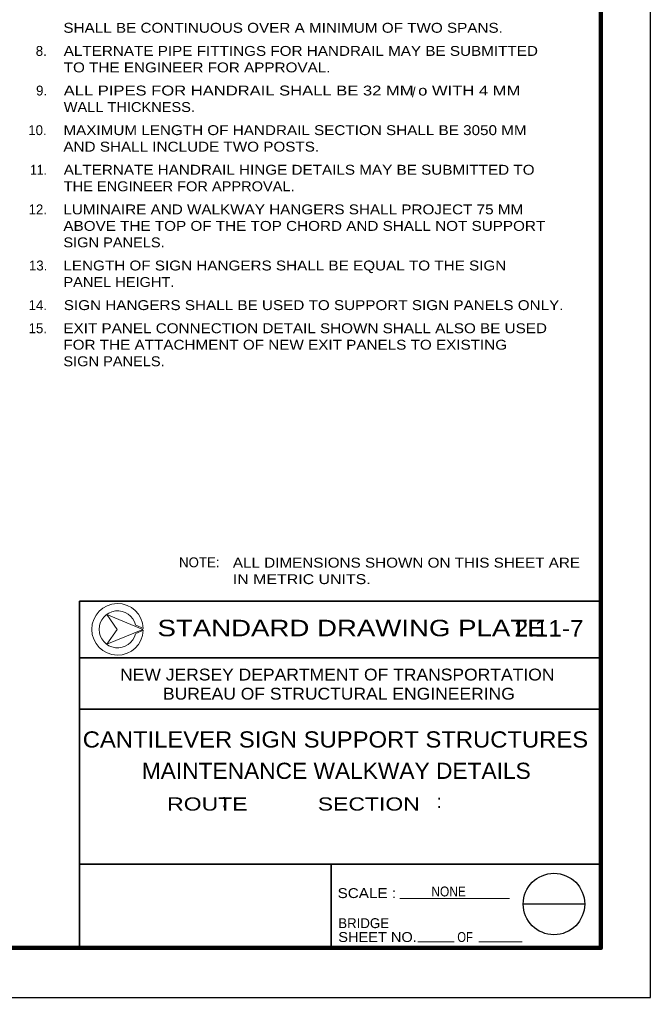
# Model space of a CAD drawing. Extents: x 312601.858 to 312602.699, y 144420.109 to 144420.704.
# Drawn here: x 312602.5078 to 312602.6988, y 144420.1095 to 144420.4057 of the extents above; entities that cross this region are included whole.
import ezdxf
from ezdxf.enums import TextEntityAlignment as Align

# ---------------------------------------------------------------- set-up
doc = ezdxf.new("R2010")
doc.units = 0
doc.header["$LTSCALE"] = 0.0012
for name, color, linetype, lineweight in [('1', 7, 'Continuous', 13), ('2', 7, 'Continuous', 13), ('39', 7, 'Continuous', 13), ('4', 7, 'Continuous', 13)]:
    doc.layers.add(name, color=color, linetype=linetype, lineweight=lineweight)

msp = doc.modelspace()

# ---------------------------------------------------------------- linework, layer by layer
at = {"layer": '1'}
msp.add_line((312602.543, 144420.2197), (312602.5453, 144420.2207), dxfattribs=at)
for points in [[(312602.5451, 144420.221), (312602.5342, 144420.2255), (312602.5451, 144420.221)], [(312602.5453, 144420.2213), (312602.543, 144420.2223), (312602.5429, 144420.2223)]]:
    msp.add_lwpolyline(points, dxfattribs=at)
for points in [[(312602.5451, 144420.221), (312602.5342, 144420.2255), (312602.5374, 144420.221), (312602.5342, 144420.2165)], [(312602.5374, 144420.221), (312602.5342, 144420.2165), (312602.5451, 144420.221), (312602.5342, 144420.2255)]]:
    msp.add_lwpolyline(points, close=True, dxfattribs=at)
for radius, start, end in [(0.007803, 2.21392, 357.78608), (0.0056, 13.69411, 346.30589)]:
    msp.add_arc((312602.5375, 144420.221), radius, start, end, dxfattribs=at)
at = {"layer": '39', "lineweight": 35}
for p, q in [((312602.526, 144420.1245), (312602.526, 144420.2295)), ((312602.526, 144420.2295), (312602.6838, 144420.2295)), ((312602.6838, 144420.2297), (312602.6838, 144420.1247)), ((312602.6838, 144420.2297), (312602.6838, 144420.1247)), ((312602.6838, 144420.2295), (312602.6838, 144420.1245)), ((312602.526, 144420.2124), (312602.6838, 144420.2124)), ((312602.526, 144420.1968), (312602.6838, 144420.1968)), ((312602.526, 144420.1499), (312602.6838, 144420.1499)), ((312602.6022, 144420.1248), (312602.6022, 144420.1499))]:
    msp.add_line(p, q, dxfattribs=at)
at = {"layer": '39'}
for p, q in [((312602.6022, 144420.1499), (312602.6838, 144420.1499)), ((312602.6022, 144420.1248), (312602.6022, 144420.1499)), ((312602.6022, 144420.1248), (312602.6022, 144420.1499)), ((312602.6229, 144420.1395), (312602.6561, 144420.1395)), ((312602.6284, 144420.1263), (312602.6394, 144420.1263)), ((312602.6469, 144420.1263), (312602.66, 144420.1263))]:
    msp.add_line(p, q, dxfattribs=at)
at = {"layer": '39', "lineweight": 25}
for p, q in [((312602.6789, 144420.1378), (312602.6603, 144420.1378)), ((312602.452, 144420.1245), (312602.6838, 144420.1245))]:
    msp.add_line(p, q, dxfattribs=at)
msp.add_lwpolyline([(312601.8578, 144420.1095), (312602.6988, 144420.1095), (312602.6988, 144420.7035)], dxfattribs=at)
at = {"layer": '39', "lineweight": 158}
msp.add_lwpolyline([(312601.9088, 144420.1245), (312602.6838, 144420.1245), (312602.6838, 144420.6645)], dxfattribs=at)
at = {"layer": '39'}
msp.add_lwpolyline([(312602.5451, 144420.221), (312602.5342, 144420.2255), (312602.5374, 144420.221), (312602.5342, 144420.2165)], close=True, dxfattribs=at)
at = {"layer": '39', "lineweight": 25}
msp.add_circle((312602.6696, 144420.1378), 0.0093, dxfattribs=at)

# ---------------------------------------------------------------- texts
at = {"layer": '2'}
for s, width, p in [('SHALL BE CONTINUOUS OVER A MINIMUM OF TWO SPANS.', 1.15, (312602.5211, 144420.4017)), ('ALTERNATE PIPE FITTINGS FOR HANDRAIL MAY BE SUBMITTED', 1.15, (312602.5212, 144420.3947)), ('TO THE ENGINEER FOR APPROVAL.', 1.15, (312602.5212, 144420.3897)), ('ALL PIPES FOR HANDRAIL SHALL BE 32 MM o WITH 4 MM', 1.25, (312602.5212, 144420.3827)), ('WALL THICKNESS.', 1.1, (312602.5212, 144420.3777)), ('MAXIMUM LENGTH OF HANDRAIL SECTION SHALL BE 3050 MM', 1.15, (312602.5211, 144420.3707)), ('AND SHALL INCLUDE TWO POSTS.', 1.15, (312602.5211, 144420.3657)), ('ALTERNATE HANDRAIL HINGE DETAILS MAY BE SUBMITTED TO', 1.15, (312602.5212, 144420.3587)), ('THE ENGINEER FOR APPROVAL.', 1.1, (312602.5212, 144420.3537)), ('LUMINAIRE AND WALKWAY HANGERS SHALL PROJECT 75 MM', 1.15, (312602.5211, 144420.3467)), ('ABOVE THE TOP OF THE TOP CHORD AND SHALL NOT SUPPORT', 1.15, (312602.5211, 144420.3417)), ('SIGN PANELS.', 1.1, (312602.5211, 144420.3367)), ('LENGTH OF SIGN HANGERS SHALL BE EQUAL TO THE SIGN', 1.15, (312602.5211, 144420.3297)), ('PANEL HEIGHT.', 1.1, (312602.5211, 144420.3247)), ('EXIT PANEL CONNECTION DETAIL SHOWN SHALL ALSO BE USED', 1.15, (312602.5211, 144420.3107)), ('FOR THE ATTACHMENT OF NEW EXIT PANELS TO EXISTING', 1.15, (312602.5211, 144420.3057)), ('SIGN PANELS.', 1.1, (312602.5211, 144420.3007))]:
    msp.add_text(s, height=0.003, dxfattribs=dict(at, width=width)).set_placement(p)
for s, p in [('8.', (312602.5144, 144420.3947)), ('9.', (312602.5145, 144420.3827)), ('/', (312602.62715, 144420.3822)), ('10.', (312602.51325, 144420.3707)), ('12.', (312602.51335, 144420.3467)), ('13.', (312602.51345, 144420.3297)), ('14.', (312602.51335, 144420.3177)), ('15.', (312602.51335, 144420.3107))]:
    msp.add_text(s, height=0.003, dxfattribs=at).set_placement(p, align=Align.CENTER)
for s, height, width, p in [('11.', 0.003, 0.9, (312602.51355, 144420.3587)), ('SIGN HANGERS SHALL BE USED TO SUPPORT SIGN PANELS ONLY.', 0.003, 1.15, (312602.59685, 144420.3177)), ('2.11-7', 0.005, 1.1, (312602.6681, 144420.2188)), ('CANTILEVER SIGN SUPPORT STRUCTURES', 0.0049, 1.1, (312602.60345, 144420.1852)), ('MAINTENANCE WALKWAY DETAILS', 0.0049, 1.05, (312602.6037, 144420.1757)), ('NONE', 0.003, 0.9, (312602.6377, 144420.1401))]:
    msp.add_text(s, height=height, dxfattribs=dict(at, width=width)).set_placement(p, align=Align.CENTER)
at = {"layer": '39'}
for s, height, width, p in [('STANDARD DRAWING PLATE       ', 0.005, 1.25, (312602.61645, 144420.2189)), ('NEW JERSEY DEPARTMENT OF TRANSPORTATION', 0.003599, 1.1, (312602.604, 144420.2055)), ('BUREAU OF STRUCTURAL ENGINEERING', 0.0036, 1.1, (312602.6045, 144420.1997)), ('ROUTE           SECTION', 0.004, 1.3, (312602.59075, 144420.1661)), ('SCALE :', 0.003, 1.15, (312602.61295, 144420.1396)), ('OF', 0.003, 0.85, (312602.6427, 144420.1263))]:
    msp.add_text(s, height=height, dxfattribs=dict(at, width=width)).set_placement(p, align=Align.CENTER)
for p in [(312602.569737, 144420.1671), (312602.634837, 144420.1669)]:
    msp.add_text(':', height=0.004, dxfattribs=at).set_placement(p, align=Align.CENTER)
msp.add_text('BRIDGE', height=0.003, dxfattribs=at).set_placement((312602.6043, 144420.1305))
at = {"layer": '39', "width": 1.1}
msp.add_text('SHEET NO.', height=0.003, dxfattribs=at).set_placement((312602.6043, 144420.1263))
at = {"layer": '4'}
msp.add_text('NOTE:', height=0.003, dxfattribs=at).set_placement((312602.5561, 144420.2398))
for s, width, p in [('ALL DIMENSIONS SHOWN ON THIS SHEET ARE', 1.15, (312602.5724, 144420.2397)), ('IN METRIC UNITS.', 1.2, (312602.5724, 144420.2347))]:
    msp.add_text(s, height=0.003, dxfattribs=dict(at, width=width)).set_placement(p)

doc.saveas('drawing.dxf')
